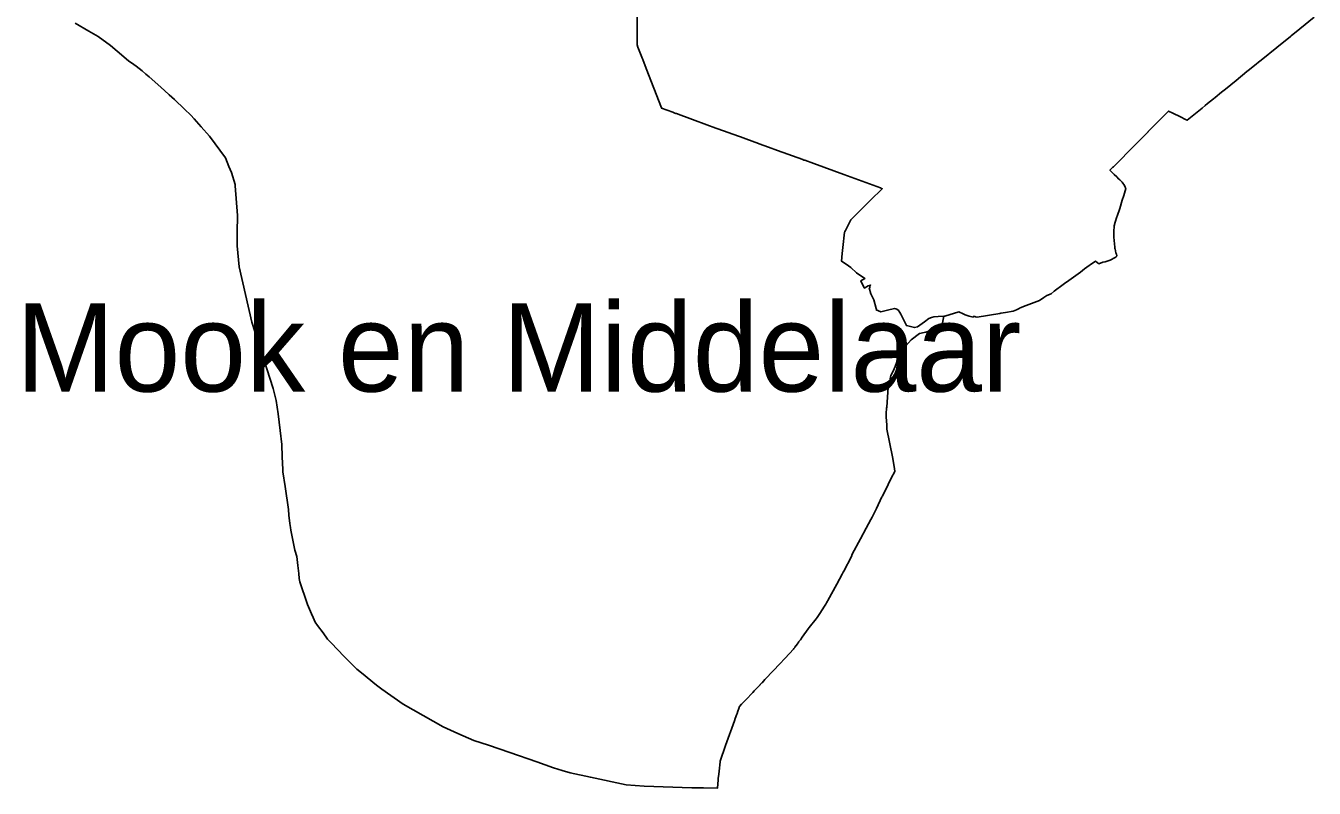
# Model space of a CAD drawing. Extents: x 113371 to 291721, y 393993 to 520143.
# Drawn here: x 187844 to 195132, y 414477 to 418792 of the extents above; entities that cross this region are included whole.
import ezdxf

# ---------------------------------------------------------------- set-up
doc = ezdxf.new("R2010")
doc.units = 0
doc.layers.add('Default', color=7, linetype='Continuous')
doc.layers.add('plaatsnamen', color=7, linetype='Continuous')

msp = doc.modelspace()

# ---------------------------------------------------------------- linework, layer by layer
at = {"layer": 'Default'}
for points in [[(192246.415625, 418031.5225), (192245.295625, 418031.9325), (192240.775625, 418033.5725), (192238.865625, 418034.2725), (192096.095625, 418086.3425), (192044.725625, 418105.0725), (191992.245625, 418124.1325), (191987.535625, 418125.8425), (191916.775625, 418151.5325), (191910.235625, 418153.9125), (191906.345625, 418155.3325), (191726.675625, 418220.7625), (191716.765625, 418224.3725), (191711.705625, 418226.2125), (191599.825625, 418266.9625), (191532.985625, 418291.5625), (191529.735625, 418292.7625), (191524.445625, 418294.7125), (191520.345625, 418296.2225), (191515.685625, 418297.9325), (191502.945625, 418302.6325), (191438.775625, 418326.3525), (191438.565625, 418326.9025), (191352.605625, 418550.6125), (191333.215625, 418601.0825), (191331.585625, 418605.3125), (191306.145625, 418671.5425), (191301.165625, 418684.5225), (191301.185625, 418706.0825), (191301.815625, 418894.1525)], [(191301.815625, 418894.1525), (191301.185625, 418706.0825), (191301.165625, 418684.5225), (191306.145625, 418671.5425)], [(188122.585625, 418807.0525), (188200.145625, 418762.0525), (188252.985625, 418730.3025), (188322.005625, 418680.6525), (188398.365625, 418615.4825), (188413.125625, 418603.2125), (188423.985625, 418593.5825), (188453.915625, 418573.2725), (188467.115625, 418563.7225), (188501.215625, 418536.0925), (188522.675625, 418517.7525), (188540.765625, 418502.2925), (188590.665625, 418459.1625), (188627.895625, 418426.2925), (188654.765625, 418401.7625), (188669.975625, 418387.6425), (188683.875625, 418374.7225), (188741.415625, 418320.0125), (188776.955625, 418286.2125), (188796.025625, 418264.5425)], [(194805.925625, 418576.8825), (194815.025625, 418584.2225), (194815.765625, 418584.8125), (194830.895625, 418597.0125), (194920.845625, 418669.5125), (194996.585625, 418730.6825), (194996.775625, 418730.8525), (195000.805625, 418734.4425), (195050.795625, 418774.6125), (195131.575625, 418839.9625)], [(191306.145625, 418671.5425), (191331.585625, 418605.3125), (191333.215625, 418601.0825), (191352.605625, 418550.6125), (191438.565625, 418326.9025), (191438.775625, 418326.3525), (191502.945625, 418302.6325), (191515.685625, 418297.9325), (191520.345625, 418296.2225), (191524.445625, 418294.7125), (191529.735625, 418292.7625), (191532.985625, 418291.5625), (191599.825625, 418266.9625), (191711.705625, 418226.2125), (191716.765625, 418224.3725), (191726.675625, 418220.7625), (191906.345625, 418155.3325), (191910.235625, 418153.9125), (191916.775625, 418151.5325), (191987.535625, 418125.8425), (191992.245625, 418124.1325), (192044.725625, 418105.0725), (192096.095625, 418086.3425), (192238.865625, 418034.2725), (192240.775625, 418033.5725), (192245.295625, 418031.9325), (192246.415625, 418031.5225), (192248.435625, 418030.7825), (192248.975625, 418030.5825), (192249.505625, 418030.3925), (192300.355625, 418011.8425), (192471.605625, 417949.3925), (192678.225625, 417874.0425), (192683.935625, 417871.4025), (192687.825625, 417869.6025), (192685.335625, 417867.1825), (192685.035625, 417866.8825), (192675.465625, 417857.6025)], [(193999.755625, 417950.6625), (193976.025625, 417974.1025), (193987.385625, 417985.6925), (193992.855625, 417991.2425), (193993.125625, 417991.5225), (193995.435625, 417993.8525), (194120.245625, 418120.0225), (194191.625625, 418192.3625), (194192.675625, 418193.3925), (194199.585625, 418200.1925), (194200.395625, 418201.0225), (194233.305625, 418234.4125), (194233.825625, 418234.9325), (194257.565625, 418258.8625), (194259.485625, 418260.7925), (194259.705625, 418261.0125), (194260.875625, 418262.2025), (194283.155625, 418284.7825), (194307.405625, 418309.2425), (194330.965625, 418297.8325), (194375.145625, 418275.8925), (194402.735625, 418261.9325), (194412.185625, 418256.9125), (194431.185625, 418271.9425), (194469.845625, 418303.4625), (194497.975625, 418326.3925), (194515.055625, 418340.3925), (194528.685625, 418351.5725), (194562.265625, 418378.7925), (194570.635625, 418385.5725), (194607.125625, 418415.1225), (194629.855625, 418433.5725), (194690.635625, 418482.5325), (194690.895625, 418482.7425), (194750.365625, 418532.4425), (194750.935625, 418532.9025), (194765.365625, 418544.4425), (194805.925625, 418576.8825)], [(188796.025625, 418264.5425), (188835.415625, 418219.7725), (188881.885625, 418167.3825), (188973.805625, 418045.0225), (188992.715625, 417995.9925), (189006.485625, 417961.1525), (189027.755625, 417893.6725), (189028.175625, 417885.1825), (189040.415625, 417718.1225), (189039.435625, 417622.5925), (189038.645625, 417546.0025), (189049.655625, 417427.3325), (189121.615625, 417115.0625), (189243.555625, 416739.6625), (189259.765625, 416672.1925), (189271.175625, 416596.4325), (189281.765625, 416501.6625), (189291.635625, 416422.9725), (189294.325625, 416352.9325), (189296.945625, 416281.6425), (189297.235625, 416273.7525), (189298.135625, 416267.7525), (189310.775625, 416184.2625), (189329.075625, 416054.7825), (189331.965625, 416021.8725), (189337.225625, 415975.2425), (189340.795625, 415952.7425), (189342.885625, 415937.0225), (189352.175625, 415891.1325), (189365.465625, 415824.3825), (189375.865625, 415788.2925), (189383.155625, 415737.3025), (189387.465625, 415692.5925), (189390.275625, 415663.4725), (189393.785625, 415644.7925), (189435.835625, 415522.4725), (189437.735625, 415517.7525), (189459.295625, 415465.1225)], [(192623.075625, 417274.4525), (192614.295625, 417308.0225), (192618.115625, 417309.5325), (192618.425625, 417320.8425), (192621.785625, 417324.4525), (192608.475625, 417320.9325), (192599.745625, 417315.4525), (192587.325625, 417307.7825), (192584.955625, 417311.0525), (192567.665625, 417346.5825), (192566.805625, 417348.3425), (192589.935625, 417361.8625), (192541.555625, 417393.6525), (192510.905625, 417424.1725), (192483.865625, 417442.1125), (192457.815625, 417459.5525), (192462.065625, 417503.5725), (192465.295625, 417537.0325), (192473.675625, 417623.3825), (192476.865625, 417626.3325), (192477.365625, 417627.3425), (192479.955625, 417632.5725), (192505.025625, 417683.1525), (192510.615625, 417694.3325), (192586.495625, 417769.5825), (192633.305625, 417815.9525), (192675.465625, 417857.6025), (192685.035625, 417866.8825), (192685.335625, 417867.1825), (192687.825625, 417869.6025), (192683.935625, 417871.4025), (192678.225625, 417874.0425), (192471.605625, 417949.3925), (192300.355625, 418011.8425), (192249.505625, 418030.3925), (192248.975625, 418030.5825), (192248.435625, 418030.7825), (192246.415625, 418031.5225)], [(193912.575625, 417444.2925), (193935.295625, 417453.3925), (193949.835625, 417456.1325), (193961.195625, 417459.5425), (193977.515625, 417464.6825), (194005.135625, 417480.6725), (194005.645625, 417480.9725), (194010.735625, 417483.4225), (194012.825625, 417485.3325), (194013.645625, 417487.2025), (194014.095625, 417490.6025), (194012.235625, 417499.3725), (194009.865625, 417507.8225), (194004.725625, 417529.1325), (194004.535625, 417530.2825), (194003.175625, 417538.5425), (193998.435625, 417595.6625), (193998.205625, 417600.8925), (193998.245625, 417611.4325), (193998.355625, 417628.1125), (193998.555625, 417636.6125), (193999.035625, 417647.6625), (193999.555625, 417659.7425), (194006.505625, 417680.0125), (194015.825625, 417710.4925), (194017.265625, 417715.1825), (194031.165625, 417758.6825), (194045.465625, 417804.8125), (194053.795625, 417831.2725), (194066.575625, 417871.8625), (194062.855625, 417879.3925), (194057.855625, 417888.4825), (194044.805625, 417907.1525), (194039.485625, 417912.1925), (194031.165625, 417920.0925), (194024.345625, 417926.4525), (194014.215625, 417936.4025), (193999.755625, 417950.6625)], [(192675.465625, 417857.6025), (192633.305625, 417815.9525), (192586.495625, 417769.5825), (192510.615625, 417694.3325), (192505.025625, 417683.1525), (192479.955625, 417632.5725), (192477.365625, 417627.3425), (192476.865625, 417626.3325), (192473.675625, 417623.3825), (192465.295625, 417537.0325), (192462.065625, 417503.5725), (192457.815625, 417459.5525), (192483.865625, 417442.1125), (192510.905625, 417424.1725), (192541.555625, 417393.6525), (192589.935625, 417361.8625), (192566.805625, 417348.3425), (192567.665625, 417346.5825), (192584.955625, 417311.0525), (192587.325625, 417307.7825), (192599.745625, 417315.4525), (192608.475625, 417320.9325), (192621.785625, 417324.4525), (192618.425625, 417320.8425), (192618.115625, 417309.5325), (192614.295625, 417308.0225), (192623.075625, 417274.4525), (192639.895625, 417240.8325), (192653.365625, 417191.6225), (192654.825625, 417185.4425), (192654.545625, 417183.9825), (192680.685625, 417173.5425), (192717.455625, 417182.3325), (192756.905625, 417191.9425), (192765.035625, 417189.5825), (192770.725625, 417187.9925), (192773.315625, 417187.0425), (192781.315625, 417180.0925)], [(193036.895625, 417148.4525), (193041.575625, 417148.7225), (193121.335625, 417173.7625), (193125.015625, 417171.8025), (193142.285625, 417163.4025), (193152.885625, 417158.2325), (193157.285625, 417156.1425), (193168.695625, 417152.6025), (193179.155625, 417149.2025), (193202.335625, 417143.3025), (193203.335625, 417147.5725), (193211.505625, 417145.7425), (193214.875625, 417144.9925), (193224.565625, 417142.5425), (193353.255625, 417163.9025), (193353.675625, 417163.9725), (193359.095625, 417164.8725), (193385.435625, 417169.2525), (193427.855625, 417176.3125), (193437.675625, 417180.0425), (193447.575625, 417184.1825), (193462.625625, 417192.6925), (193468.785625, 417195.1325), (193502.975625, 417208.6625), (193577.415625, 417238.0525), (193602.855625, 417254.1525), (193619.455625, 417264.6525), (193643.455625, 417275.3925), (193661.035625, 417289.2125), (193711.345625, 417328.2725), (193719.295625, 417333.7325), (193742.925625, 417350.7825), (193808.675625, 417398.0325), (193833.005625, 417415.6525), (193859.335625, 417434.7325), (193864.695625, 417438.6125), (193893.615625, 417459.5525), (193912.575625, 417444.2925)], [(192788.715625, 416949.7125), (192793.985625, 416954.1925), (192798.335625, 416957.6325), (192801.555625, 416959.5425), (192805.085625, 416962.8825), (192808.955625, 416965.3925), (192850.795625, 417014.3625), (192899.605625, 417049.8125), (192924.665625, 417055.5625), (192935.335625, 417057.8525), (192945.905625, 417061.9125), (192969.215625, 417073.5225), (193011.195625, 417095.7925), (193028.075625, 417110.1825), (193036.895625, 417148.4525), (193003.895625, 417146.5225), (192979.765625, 417144.8325), (192967.035625, 417140.7425), (192952.315625, 417135.8225), (192926.725625, 417116.4525), (192887.825625, 417087.7125), (192871.055625, 417084.3925), (192824.835625, 417095.3125), (192806.325625, 417132.6125), (192793.995625, 417159.7825), (192782.765625, 417178.0025), (192781.315625, 417180.0925), (192773.315625, 417187.0425), (192770.725625, 417187.9925), (192765.035625, 417189.5825), (192756.905625, 417191.9425), (192717.455625, 417182.3325), (192680.685625, 417173.5425), (192654.545625, 417183.9825), (192654.825625, 417185.4425), (192653.365625, 417191.6225), (192639.895625, 417240.8325), (192623.075625, 417274.4525)], [(192781.315625, 417180.0925), (192782.765625, 417178.0025), (192793.995625, 417159.7825), (192806.325625, 417132.6125), (192824.835625, 417095.3125), (192871.055625, 417084.3925), (192887.825625, 417087.7125), (192926.725625, 417116.4525), (192952.315625, 417135.8225), (192967.035625, 417140.7425), (192979.765625, 417144.8325), (193003.895625, 417146.5225), (193036.895625, 417148.4525)], [(192623.275625, 415998.7525), (192630.385625, 416011.1225), (192654.935625, 416061.1225), (192686.465625, 416125.3525), (192688.675625, 416129.8425), (192721.315625, 416196.3225), (192723.685625, 416201.1625), (192724.455625, 416202.7325), (192738.835625, 416232.1025), (192760.025625, 416270.4525), (192757.445625, 416285.6725), (192746.105625, 416352.7425), (192714.535625, 416508.7425), (192713.395625, 416534.0125), (192710.985625, 416576.7925), (192710.955625, 416589.1725), (192710.675625, 416594.8725), (192710.605625, 416596.0925), (192710.495625, 416598.4325), (192713.005625, 416628.4425), (192713.415625, 416633.7025), (192715.645625, 416662.5625), (192722.245625, 416747.2725), (192720.595625, 416764.3225), (192723.625625, 416764.7425), (192729.525625, 416765.4725), (192731.965625, 416794.5325), (192737.505625, 416813.5425), (192750.725625, 416836.4125), (192761.905625, 416864.4325), (192769.245625, 416884.8525), (192772.495625, 416902.6225), (192771.625625, 416922.8025), (192775.195625, 416935.6825), (192778.225625, 416940.3725), (192780.755625, 416943.8825), (192783.455625, 416945.5525), (192788.715625, 416949.7125)], [(192138.615625, 415213.6325), (192185.595625, 415263.5525), (192186.245625, 415264.2425), (192186.665625, 415264.6825), (192188.765625, 415267.6425), (192193.685625, 415274.5625), (192193.735625, 415274.6425), (192194.325625, 415275.4725), (192207.915625, 415294.6025), (192209.055625, 415296.1925), (192209.115625, 415296.2925), (192209.985625, 415297.5025), (192210.145625, 415297.7425), (192216.505625, 415306.6025), (192216.655625, 415306.8125), (192220.035625, 415311.4825), (192224.775625, 415318.0425), (192234.605625, 415331.6625), (192268.535625, 415379.8125), (192275.065625, 415387.2625), (192315.025625, 415436.4325), (192320.195625, 415443.0825), (192324.395625, 415449.3125), (192334.895625, 415465.9725), (192360.705625, 415506.8025), (192368.245625, 415518.7425), (192373.455625, 415527.3125), (192378.355625, 415536.0325), (192380.595625, 415540.1425), (192430.465625, 415631.4525), (192460.825625, 415689.0125), (192466.165625, 415699.1425), (192469.945625, 415706.3225), (192513.415625, 415788.9925), (192517.535625, 415801.0925), (192564.145625, 415888.1625), (192597.005625, 415949.6225), (192623.275625, 415998.7525)], [(189459.295625, 415465.1225), (189468.655625, 415443.9825), (189474.285625, 415431.1725), (189480.365625, 415417.5225), (189493.675625, 415397.9425), (189524.775625, 415356.8625), (189550.995625, 415321.4325), (189572.685625, 415298.6725), (189643.025625, 415225.2725), (189717.005625, 415152.0225), (189742.185625, 415129.7425), (189827.665625, 415061.3125), (189857.615625, 415037.3225), (189977.465625, 414953.4025), (190204.825625, 414824.0425), (190286.515625, 414786.3625), (190378.595625, 414747.7425), (190461.505625, 414720.3625), (190581.845625, 414679.3625), (190733.445625, 414627.7225), (190828.165625, 414592.3125), (190877.265625, 414578.0025), (190923.755625, 414564.4525), (191037.095625, 414540.0225), (191239.715625, 414496.5025), (191340.915625, 414488.7025), (191610.615625, 414480.6125), (191676.585625, 414479.1725), (191755.915625, 414477.4425), (191759.765625, 414525.3625), (191760.085625, 414526.7025), (191760.625625, 414532.2425)], [(191760.625625, 414532.2425), (191763.145625, 414557.9325), (191764.775625, 414573.5925), (191770.425625, 414627.7425), (191770.685625, 414630.2025), (191802.095625, 414719.1725), (191851.815625, 414858.6025), (191856.755625, 414872.0925), (191856.935625, 414872.6025), (191865.675625, 414897.4125), (191866.885625, 414900.8425), (191866.975625, 414901.0925), (191868.475625, 414905.3225), (191869.335625, 414907.7525), (191869.595625, 414908.4825), (191878.895625, 414934.7425), (191879.115625, 414935.3825), (191880.755625, 414940.0125), (191892.415625, 414952.3325), (191900.125625, 414960.4925), (191900.435625, 414960.8125), (191915.055625, 414976.2625), (191917.095625, 414978.4125), (191955.255625, 415018.6625), (191955.535625, 415018.9725), (191964.195625, 415028.0925), (191984.515625, 415049.5225), (191986.165625, 415051.2625), (191997.575625, 415063.3825), (191997.805625, 415063.6125), (192006.915625, 415073.2825), (192008.165625, 415074.6125), (192024.585625, 415092.1325), (192073.555625, 415144.3525), (192107.115625, 415180.1125), (192107.175625, 415180.1725), (192138.335625, 415213.3425), (192138.615625, 415213.6325)]]:
    msp.add_lwpolyline(points, dxfattribs=at)

# ---------------------------------------------------------------- texts
at = {"layer": 'plaatsnamen'}
msp.add_text('Mook en Middelaar', height=500, dxfattribs=at).set_placement((187788.653279, 416721.905))

doc.saveas('drawing.dxf')
